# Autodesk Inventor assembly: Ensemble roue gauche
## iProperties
Author: Flavien MARTY
Shininess: 21.0
PropertySet Name: _Private Model Information
Created: 2001-10
Part Number: Ensemble roue gauche
Document SubType Name: Assemblage
Designer: Flavien MARTY
Control State: 0
Master: False
Checked Out: False
PropertySet Name: Design Tracking Control
Density: 0.0
Volumn: 0.0
Area: 0.0
PropertySet Name: Model Information
